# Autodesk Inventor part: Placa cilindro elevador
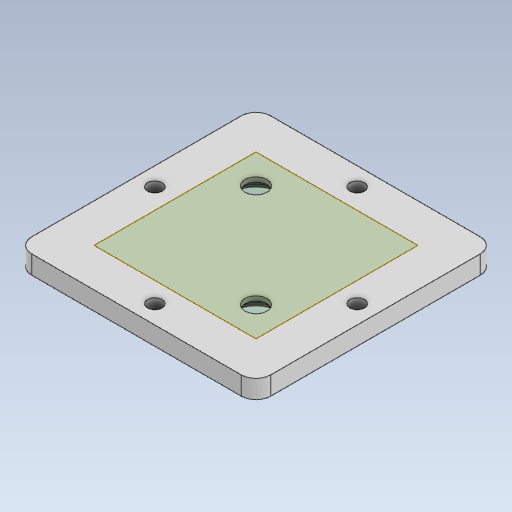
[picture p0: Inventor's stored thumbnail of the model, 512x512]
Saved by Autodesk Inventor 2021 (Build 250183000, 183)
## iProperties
Created: 2021-02
Part Number: Placa cilindro elevador
Material: Genérico
Document SubType Name: Modeling
Designer: ATOUZA
Density: 1 g/cm^3
Appearance: Valor por defecto
Author: ATOUZA
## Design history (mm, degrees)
node "Plano de trabajo1"
extrude "Extrusión1" new body sketch "Boceto1" distance "d4" = 5; taper "d5" = 0 deg
sketch "Boceto2"
  geometry: C1 r 3 at (-14, -14) reference; C2 r 3 at (14, 14) reference; 3 further points
  constraints: 2 coincident
hole "Agujero1" sketch "Boceto2" at (-14, -14), (14, 14) diameter "d6" = 6; stored, may be unused: countersink angle "d10" = 90 deg, drill point angle "d12" = 118 deg; dims "d7" = 6, "d8" = 13.5, "d9" = 2, "d11" = 8
fillet "Empalme1" dims "d19" = 4
node "Sólido1"
other parameters: "d0" = 65, "d1" = 65, "d13" = 4, "d14" = 5, "d17" = 360 deg (derived), "d20" = 12.5, "d21" = 12.5
